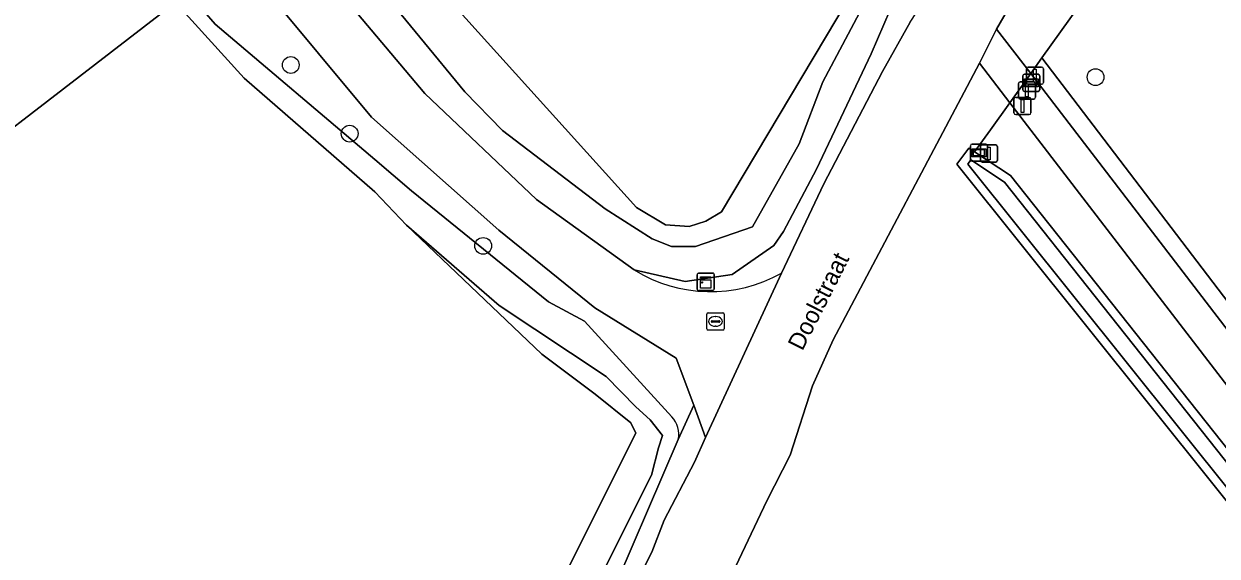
# Model space of a CAD drawing. Extents: x 164494 to 166241, y 382475 to 384495.
# Drawn here: x 164979.6 to 165049.1, y 382956.1 to 382987.1 of the extents above; entities that cross this region are included whole.
import ezdxf

# ---------------------------------------------------------------- set-up
doc = ezdxf.new("R2010")
doc.units = 0
for name, color, linetype in [('IMGEO_Afsluitpaal', 7, 'Continuous'), ('IMGEO_Boom', 7, 'Continuous'), ('IMGEO_Erf', 7, 'Continuous'), ('IMGEO_Grasland_agrarisch', 7, 'Continuous'), ('IMGEO_Grasland_overig', 7, 'Continuous'), ('IMGEO_Groenvoorziening', 7, 'Continuous'), ('IMGEO_Hek', 7, 'Continuous'), ('IMGEO_Informatiebord', 7, 'Continuous'), ('IMGEO_Kast', 7, 'Continuous'), ('IMGEO_Oever', 7, 'Continuous'), ('IMGEO_Openbare_ruimte_label', 7, 'Continuous'), ('IMGEO_Rijbaan_lokaal_gesloten', 7, 'Continuous'), ('IMGEO_Rioolput', 7, 'Continuous'), ('IMGEO_Straatnaambord', 7, 'Continuous'), ('IMGEO_Voetpad_halfverhard', 7, 'Continuous'), ('IMGEO_Waterloop', 7, 'Continuous')]:
    doc.layers.add(name, color=color, linetype=linetype)

msp = doc.modelspace()

# ---------------------------------------------------------------- linework, layer by layer
at = {"layer": 'IMGEO_Afsluitpaal'}
for p, q in [((165037.945, 382983.664), (165037.945, 382984.464)), ((165037.945, 382984.464), (165037.945, 382983.664)), ((165038.045, 382984.564), (165038.835, 382984.564)), ((165038.835, 382984.564), (165038.045, 382984.564)), ((165038.935, 382984.464), (165038.935, 382983.664)), ((165038.935, 382983.664), (165038.935, 382984.464)), ((165037.48, 382982.803), (165037.48, 382983.603)), ((165037.48, 382983.603), (165037.48, 382982.803)), ((165037.58, 382983.703), (165038.37, 382983.703)), ((165038.37, 382983.703), (165037.58, 382983.703)), ((165038.835, 382983.564), (165038.045, 382983.564)), ((165038.045, 382983.564), (165038.835, 382983.564)), ((165038.47, 382983.603), (165038.47, 382982.803)), ((165038.47, 382982.803), (165038.47, 382983.603)), ((165037.224, 382981.896), (165037.224, 382982.696)), ((165037.224, 382982.696), (165037.224, 382981.896)), ((165037.324, 382982.796), (165038.114, 382982.796)), ((165038.114, 382982.796), (165037.324, 382982.796)), ((165038.37, 382982.703), (165037.58, 382982.703)), ((165037.58, 382982.703), (165038.37, 382982.703)), ((165038.214, 382982.696), (165038.214, 382981.896)), ((165038.214, 382981.896), (165038.214, 382982.696)), ((165038.114, 382981.796), (165037.324, 382981.796)), ((165037.324, 382981.796), (165038.114, 382981.796)), ((165035.37, 382980.028), (165036.16, 382980.028)), ((165036.16, 382980.028), (165035.37, 382980.028)), ((165035.27, 382979.128), (165035.27, 382979.928)), ((165035.27, 382979.928), (165035.27, 382979.128)), ((165036.26, 382979.928), (165036.26, 382979.128)), ((165036.26, 382979.128), (165036.26, 382979.928)), ((165036.16, 382979.028), (165035.37, 382979.028)), ((165035.37, 382979.028), (165036.16, 382979.028))]:
    msp.add_line(p, q, dxfattribs=at)
for points in [[(165038.365, 382984.439), (165038.515, 382984.439), (165038.515, 382983.689), (165038.365, 382983.689), (165038.365, 382984.439)], [(165037.9, 382983.578), (165038.05, 382983.578), (165038.05, 382982.828), (165037.9, 382982.828), (165037.9, 382983.578)], [(165037.644, 382982.671), (165037.794, 382982.671), (165037.794, 382981.921), (165037.644, 382981.921), (165037.644, 382982.671)], [(165035.69, 382979.903), (165035.84, 382979.903), (165035.84, 382979.153), (165035.69, 382979.153), (165035.69, 382979.903)]]:
    msp.add_lwpolyline(points, dxfattribs=at)
for centre, start, end in [((165038.045, 382984.464), 90, 180), ((165038.045, 382984.464), 90, 180), ((165038.835, 382984.464), 0, 90), ((165038.835, 382984.464), 360, 90), ((165037.58, 382983.603), 90, 180), ((165037.58, 382983.603), 90, 180), ((165038.045, 382983.664), 180, 270), ((165038.045, 382983.664), 180, 270), ((165038.37, 382983.603), 0, 90), ((165038.37, 382983.603), 360, 90), ((165038.835, 382983.664), 270, 0), ((165038.835, 382983.664), 270, 0), ((165037.58, 382982.803), 180, 270), ((165037.58, 382982.803), 180, 270), ((165038.37, 382982.803), 270, 0), ((165038.37, 382982.803), 270, 0), ((165037.324, 382982.696), 90, 180), ((165037.324, 382982.696), 90, 180), ((165038.114, 382982.696), 0, 90), ((165038.114, 382982.696), 360, 90), ((165037.324, 382981.896), 180, 270), ((165037.324, 382981.896), 180, 270), ((165038.114, 382981.896), 270, 0), ((165038.114, 382981.896), 270, 0), ((165035.37, 382979.928), 90, 180), ((165035.37, 382979.928), 90, 180), ((165036.16, 382979.928), 0, 90), ((165036.16, 382979.928), 360, 90), ((165035.37, 382979.128), 180, 270), ((165035.37, 382979.128), 180, 270), ((165036.16, 382979.128), 270, 0), ((165036.16, 382979.128), 270, 0)]:
    msp.add_arc(centre, 0.1, start, end, dxfattribs=at)
at = {"layer": 'IMGEO_Boom'}
for centre in [(164995.114, 382984.685), (165041.974, 382983.978), (164998.544, 382980.686), (165006.318, 382974.144)]:
    msp.add_circle(centre, 0.489, dxfattribs=at)
at = {"layer": 'IMGEO_Erf'}
msp.add_lwpolyline([(164912.977, 383001.114), (164922.099, 383006.896), (164939.727, 382985.979), (164946.353, 382978.116), (164951.254, 382972.3), (164964.372, 382979.334), (164969.997, 382974.151), (164988.4, 382988.331), (164984.931, 382992.892), (164983.682, 382994.898), (164980.12, 383000), (164974.32, 383008.309), (164974.721, 383008.566), (164975.201, 383008.524), (164975.758, 383008.141), (164974.637, 383009.542), (164958.186, 383032.429), (164958.624, 383032.701), (164958.137, 383033.332), (164957.186, 383032.6), (164956.357, 383032.183), (164935.16, 383021.535), (164919.847, 383009.569), (164910.815, 383003.74)], close=True, dxfattribs=at)
for points in [[(165149.084, 382949.174), (165148.158, 382951.679), (165147.327, 382953.204), (165144.143, 382962.9), (165139.197, 382976.046), (165137.999, 382979.812), (165137.425, 382980.815), (165123.051, 383020.688), (165118.823, 383033.37), (165102.205, 383024.82), (165097.081, 383022.184), (165092.763, 383020.321), (165071.589, 383009.606), (165052.261, 382999.034), (165049.332, 382997.432), (165046.565, 382995.873), (165042.211, 382989.793), (165038.852, 382985.102), (165066.603, 382948.671), (165135.814, 382857.34)], [(165052.627, 382955.505), (165033.888, 382978.901), (165034.586, 382979.845), (165034.926, 382979.62), (165035.847, 382980.906), (165036.979, 382982.486), (165035.21, 382984.79), (165026.7, 382968.663), (165025.486, 382965.99), (165024.184, 382961.958), (165022.83, 382959.286), (165019.573, 382952.406)]]:
    msp.add_lwpolyline(points, dxfattribs=at)
at = {"layer": 'IMGEO_Grasland_agrarisch'}
msp.add_lwpolyline([(165015.068, 383038.527), (165009.03, 383072.591), (165000.629, 383105.28), (164935.939, 383078.318), (164941.019, 383069.044), (164942.895, 383066.027), (164962.537, 383037.482), (164965.976, 383039.437), (164978.568, 383020.55), (165001.867, 382991.222), (165015.247, 382976.375), (165016.924, 382975.368), (165018.308, 382975.284), (165019.273, 382975.578), (165020.196, 382976.123), (165027.578, 382988.518), (165024.542, 382992.255), (165022.647, 382995.737), (165020.576, 383000.76), (165019.166, 383008.34)], close=True, dxfattribs=at)
msp.add_lwpolyline([(164978.417, 382906.671), (164985.101, 382913.922), (164999.326, 382935.399), (165004.186, 382942.312), (165006.908, 382946.571), (165012.979, 382958.784), (165015.209, 382963.242), (165014.915, 382963.833), (165012.834, 382965.5), (165009.734, 382967.834), (165001.853, 382975.356), (165000, 382977.286), (164992.399, 382983.912), (164988.4, 382988.331), (164969.997, 382974.151)], dxfattribs=at)
at = {"layer": 'IMGEO_Grasland_overig'}
for points in [[(164978.086, 383017.145), (164979.731, 383014.456), (164985.246, 383006.707), (164990.786, 383000), (165000, 382989.514), (165005.249, 382983.12), (165007.435, 382980.868), (165013.428, 382976.295), (165016.158, 382974.56), (165017.274, 382974.114), (165018.674, 382974.106), (165021.998, 382975.247), (165024.724, 382980.091), (165026.086, 382983.698), (165028.222, 382987.725), (165027.578, 382988.518), (165020.196, 382976.123), (165019.273, 382975.578), (165018.308, 382975.284), (165016.924, 382975.368), (165015.247, 382976.375), (165001.867, 382991.222), (164978.568, 383020.55)], [(164979.355, 382905.468), (164980.096, 382906.311), (164980.625, 382906.982), (164988.585, 382917.085), (165002.824, 382937.566), (165009.708, 382948.007), (165016.119, 382960.789), (165016.533, 382962.376), (165016.761, 382963.095), (165016.048, 382964.005), (165015.202, 382964.763), (165013.474, 382966.537), (165007.243, 382970.671), (165001.853, 382975.356), (165009.734, 382967.834), (165012.834, 382965.5), (165014.915, 382963.833), (165015.209, 382963.242), (165012.979, 382958.784), (165006.908, 382946.571), (165004.186, 382942.312), (164999.326, 382935.399), (164985.101, 382913.922), (164978.417, 382906.671)]]:
    msp.add_lwpolyline(points, dxfattribs=at)
for points in [[(165036.209, 382986.774), (165036.165, 382986.697), (165035.21, 382984.79), (165036.979, 382982.486), (165038.196, 382984.186)], [(165134.51, 382858.521), (165038.196, 382984.186), (165036.979, 382982.486), (165132.894, 382857.571), (165133.054, 382857.617), (165134.517, 382857.699)]]:
    msp.add_lwpolyline(points, close=True, dxfattribs=at)
at = {"layer": 'IMGEO_Groenvoorziening'}
for points in [[(164993.635, 382989.092), (164981.184, 383005.457), (164974.637, 383009.542), (164975.758, 383008.141), (164981.443, 383000), (164989.425, 382988.568), (164990.716, 382987.061), (165000, 382979.175), (165002.138, 382977.359), (165010.119, 382970.888), (165012.212, 382969.763), (165017.299, 382964.177)], [(165029.565, 382984.303), (165031.181, 382987.173), (165031.885, 382988.24), (165030.215, 382989.551), (165029.549, 382990.073), (165028.73, 382988.684), (165029.536, 382988.299), (165030.019, 382987.907), (165028.915, 382985.327), (165025.735, 382978.625), (165023.796, 382974.977), (165023.232, 382974.16), (165020.824, 382972.474), (165018.088, 382972.069), (165015.116, 382972.749)], [(165017.672, 382962.855), (165018.575, 382964.865), (165017.56, 382967.611), (165012.813, 382970.534), (165007.238, 382975.053), (164999.815, 382981.64), (164993.635, 382989.092)], [(165023.682, 382972.564), (165026.15, 382977.763), (165029.565, 382984.303)], [(165012.194, 382948.488), (165016.136, 382956.304), (165016.846, 382958.16), (165018.624, 382961.546), (165019.27, 382962.984), (165018.575, 382964.865), (165017.672, 382962.855), (165013.257, 382952.601)]]:
    msp.add_lwpolyline(points, dxfattribs=at)
for points in [[(165042.211, 382989.793), (165039.621, 382992.313), (165038.284, 382990.391), (165036.209, 382986.774), (165038.196, 382984.186), (165038.852, 382985.102)], [(165038.196, 382984.186), (165134.51, 382858.521), (165134.517, 382857.699), (165135.308, 382857.48), (165135.814, 382857.34), (165066.603, 382948.671), (165038.852, 382985.102)], [(165131.232, 382857.093), (165132.894, 382857.571), (165036.979, 382982.486), (165035.847, 382980.906), (165034.926, 382979.62), (165037.013, 382978.237), (165054.29, 382956.447), (165062.249, 382947.031)]]:
    msp.add_lwpolyline(points, close=True, dxfattribs=at)
for centre, radius, start, end in [((165019.555, 382979.879), 8.399, 238.09319, 299.43236), ((165016.313, 382963.185), 1.398, 346.33974, 45.1729)]:
    msp.add_arc(centre, radius, start, end, dxfattribs=at)
at = {"layer": 'IMGEO_Hek'}
for points in [[(165038.852, 382985.102), (165066.603, 382948.671), (165135.814, 382857.34), (165135.308, 382857.48)], [(165035.847, 382980.906), (165034.926, 382979.62)]]:
    msp.add_lwpolyline(points, dxfattribs=at)
at = {"layer": 'IMGEO_Informatiebord'}
for p, q in [((165034.789, 382980.075), (165035.579, 382980.075)), ((165035.579, 382980.075), (165034.789, 382980.075)), ((165034.689, 382979.175), (165034.689, 382979.975)), ((165034.689, 382979.975), (165034.689, 382979.175)), ((165035.679, 382979.975), (165035.679, 382979.175)), ((165035.679, 382979.175), (165035.679, 382979.975)), ((165035.579, 382979.075), (165034.789, 382979.075)), ((165034.789, 382979.075), (165035.579, 382979.075))]:
    msp.add_line(p, q, dxfattribs=at)
for points in [[(165034.79, 382979.807), (165035.578, 382979.807), (165035.578, 382979.343), (165034.79, 382979.343), (165034.79, 382979.807)], [(165034.855, 382979.742), (165034.855, 382979.408), (165035.513, 382979.408), (165035.513, 382979.742), (165034.855, 382979.742)]]:
    msp.add_lwpolyline(points, dxfattribs=at)
for centre, start, end in [((165034.789, 382979.975), 90, 180), ((165034.789, 382979.975), 90, 180), ((165035.579, 382979.975), 0, 90), ((165035.579, 382979.975), 360, 90), ((165034.789, 382979.175), 180, 270), ((165034.789, 382979.175), 180, 270), ((165035.579, 382979.175), 270, 0), ((165035.579, 382979.175), 270, 0)]:
    msp.add_arc(centre, 0.1, start, end, dxfattribs=at)
at = {"layer": 'IMGEO_Kast'}
for p, q in [((165018.774, 382971.626), (165018.774, 382972.467)), ((165018.774, 382972.467), (165018.774, 382971.626)), ((165018.849, 382972.551), (165019.69, 382972.551)), ((165019.69, 382972.551), (165018.849, 382972.551)), ((165019.774, 382972.476), (165019.774, 382971.635)), ((165019.774, 382971.635), (165019.774, 382972.476)), ((165019.699, 382971.551), (165018.858, 382971.551)), ((165018.858, 382971.551), (165019.699, 382971.551))]:
    msp.add_line(p, q, dxfattribs=at)
for points in [[(165018.969, 382972.341), (165019.569, 382972.341), (165019.569, 382972.256), (165018.969, 382972.256), (165018.969, 382972.341)], [(165018.969, 382972.166), (165019.569, 382972.166), (165019.569, 382971.677), (165018.969, 382971.677), (165018.969, 382972.166)]]:
    msp.add_lwpolyline(points, dxfattribs=at)
msp.add_circle((165019.053, 382972.015), 0.0377, dxfattribs=at)
for centre, start, end in [((165018.852, 382972.473), 92.4484, 184.28452), ((165018.852, 382972.473), 92.4484, 184.28452), ((165019.696, 382972.473), 2.4484, 94.28452), ((165019.696, 382972.473), 2.4484, 94.28452), ((165018.852, 382971.629), 182.4484, 274.28452), ((165018.852, 382971.629), 182.4484, 274.28452), ((165019.696, 382971.629), 272.4484, 4.28452), ((165019.696, 382971.629), 272.4484, 4.28452)]:
    msp.add_arc(centre, 0.0779, start, end, dxfattribs=at)
at = {"layer": 'IMGEO_Oever'}
for points in [[(165101.952, 382894.428), (165055.083, 382954.346), (165054.29, 382956.447), (165037.013, 382978.237), (165034.926, 382979.62), (165034.586, 382979.845), (165033.888, 382978.901), (165052.627, 382955.505), (165053.916, 382953.022), (165087.093, 382910.831), (165121.757, 382865.311)], [(165122.323, 382865.411), (165087.497, 382911.144), (165054.348, 382953.3), (165053.058, 382955.785), (165034.533, 382978.913), (165034.709, 382979.151), (165036.663, 382977.856), (165053.84, 382956.192), (165054.632, 382954.092), (165101.546, 382894.117)]]:
    msp.add_lwpolyline(points, dxfattribs=at)
at = {"layer": 'IMGEO_Rijbaan_lokaal_gesloten'}
for points in [[(165022.83, 382959.286), (165024.184, 382961.958), (165025.486, 382965.99), (165026.7, 382968.663), (165035.21, 382984.79), (165036.165, 382986.697), (165036.209, 382986.774), (165038.284, 382990.391), (165039.621, 382992.313), (165039.627, 382992.322)], [(165031.181, 382987.173), (165029.565, 382984.303), (165026.15, 382977.763), (165023.682, 382972.564), (165019.27, 382962.984), (165018.624, 382961.546), (165016.846, 382958.16), (165016.136, 382956.304), (165012.194, 382948.488)], [(165019.573, 382952.406), (165022.83, 382959.286)]]:
    msp.add_lwpolyline(points, dxfattribs=at)
at = {"layer": 'IMGEO_Rioolput'}
for p, q in [((165019.345, 382969.318), (165019.345, 382970.17)), ((165019.42, 382970.244), (165020.272, 382970.244)), ((165019.604, 382969.738), (165019.604, 382969.75)), ((165020.042, 382969.701), (165019.644, 382969.701)), ((165019.647, 382969.787), (165020.045, 382969.787)), ((165019.833, 382970.024), (165019.858, 382970.024)), ((165020.088, 382969.75), (165020.088, 382969.738)), ((165020.346, 382970.17), (165020.346, 382969.318)), ((165020.272, 382969.244), (165019.42, 382969.244)), ((165019.856, 382969.464), (165019.831, 382969.464))]:
    msp.add_line(p, q, dxfattribs=at)
for points in [[(165019.345, 382969.318), (165019.345, 382970.17)], [(165019.42, 382970.244), (165020.272, 382970.244)], [(165020.346, 382970.17), (165020.346, 382969.318)], [(165020.272, 382969.244), (165019.42, 382969.244)]]:
    msp.add_lwpolyline(points, dxfattribs=at)
for centre, radius, start, end in [((165019.422, 382970.168), 0.0765, 91.55205, 178.44795), ((165019.422, 382970.168), 0.0765, 91.55205, 178.44795), ((165019.644, 382969.747), 0.0403, 85.87752, 175.75265), ((165019.641, 382969.737), 0.0366, 178.93798, 274.71019), ((165020.045, 382969.744), 0.043, 264.86636, 352.45326), ((165020.049, 382969.749), 0.0386, 1.73085, 96.63898), ((165020.27, 382970.168), 0.0765, 1.55205, 88.44795), ((165020.27, 382970.168), 0.0765, 1.55205, 88.44795), ((165019.422, 382969.32), 0.0765, 181.55205, 268.44795), ((165019.422, 382969.32), 0.0765, 181.55205, 268.44795), ((165020.27, 382969.32), 0.0765, 271.55205, 358.44795), ((165020.27, 382969.32), 0.0765, 271.55205, 358.44795)]:
    msp.add_arc(centre, radius, start, end, dxfattribs=at)
for centre, major_axis, ratio, start_param, end_param in [((165019.832, 382969.744), (-0.387, 0.002), 0.722429, 4.712389, 7.853982), ((165019.857, 382969.744), (-0.39, 0.002), 0.717154, 1.570796, 4.712389)]:
    msp.add_ellipse(centre, major_axis=major_axis, ratio=ratio, start_param=start_param, end_param=end_param, dxfattribs=at)
at = {"layer": 'IMGEO_Straatnaambord'}
for p, q in [((165037.735, 382983.245), (165037.735, 382984.045)), ((165037.735, 382984.045), (165037.735, 382983.245)), ((165037.835, 382984.145), (165038.625, 382984.145)), ((165038.625, 382984.145), (165037.835, 382984.145)), ((165038.725, 382984.045), (165038.725, 382983.245)), ((165038.725, 382983.245), (165038.725, 382984.045)), ((165038.625, 382983.145), (165037.835, 382983.145)), ((165037.835, 382983.145), (165038.625, 382983.145))]:
    msp.add_line(p, q, dxfattribs=at)
for points in [[(165037.836, 382983.877), (165038.624, 382983.877), (165038.624, 382983.413), (165037.836, 382983.413), (165037.836, 382983.877)], [(165037.901, 382983.812), (165037.901, 382983.478), (165038.559, 382983.478), (165038.559, 382983.812), (165037.901, 382983.812)]]:
    msp.add_lwpolyline(points, dxfattribs=at)
for centre, start, end in [((165037.835, 382984.045), 90, 180), ((165037.835, 382984.045), 90, 180), ((165038.625, 382984.045), 0, 90), ((165038.625, 382984.045), 360, 90), ((165037.835, 382983.245), 180, 270), ((165037.835, 382983.245), 180, 270), ((165038.625, 382983.245), 270, 0), ((165038.625, 382983.245), 270, 0)]:
    msp.add_arc(centre, 0.1, start, end, dxfattribs=at)
at = {"layer": 'IMGEO_Voetpad_halfverhard'}
for points in [[(165015.116, 382972.749), (165009.429, 382976.853), (165002.924, 382983.02), (164995.304, 382992.08), (164983.764, 383006.976), (164976.307, 383014.726), (164975.747, 383015.453), (164961.213, 383034.306), (164960.562, 383033.902), (164959.969, 383034.672), (164953.443, 383043.142), (164940.984, 383059.314), (164923.612, 383083.222), (164922.498, 383084.86), (164918.185, 383091.202)], [(164916.364, 383089.959), (164920.303, 383083.963), (164921.752, 383081.757), (164939.485, 383057.976), (164951.578, 383041.853), (164958.137, 383033.332), (164958.624, 383032.701), (164958.186, 383032.429), (164974.637, 383009.542), (164981.184, 383005.457), (164993.635, 382989.092), (164999.815, 382981.64), (165007.238, 382975.053), (165012.813, 382970.534), (165017.56, 382967.611), (165018.575, 382964.865), (165019.27, 382962.984), (165023.682, 382972.564)]]:
    msp.add_lwpolyline(points, dxfattribs=at)
msp.add_arc((165019.555, 382979.879), 8.399, 238.09319, 299.43236, dxfattribs=at)
at = {"layer": 'IMGEO_Waterloop'}
for points in [[(165017.299, 382964.177), (165012.212, 382969.763), (165010.119, 382970.888), (165002.138, 382977.359), (165000, 382979.175), (164990.716, 382987.061), (164989.425, 382988.568), (164981.443, 383000), (164975.758, 383008.141)], [(164995.304, 382992.08), (165002.924, 382983.02), (165009.429, 382976.853), (165015.116, 382972.749), (165018.088, 382972.069), (165020.824, 382972.474), (165023.232, 382974.16), (165023.796, 382974.977), (165025.735, 382978.625), (165028.915, 382985.327), (165030.019, 382987.907)], [(165028.222, 382987.725), (165026.086, 382983.698), (165024.724, 382980.091), (165021.998, 382975.247), (165018.674, 382974.106), (165017.274, 382974.114), (165016.158, 382974.56), (165013.428, 382976.295), (165007.435, 382980.868), (165005.249, 382983.12), (165000, 382989.514)], [(164988.4, 382988.331), (164992.399, 382983.912), (165000, 382977.286), (165001.853, 382975.356), (165007.243, 382970.671), (165013.474, 382966.537), (165015.202, 382964.763), (165016.048, 382964.005), (165016.761, 382963.095), (165016.533, 382962.376), (165016.119, 382960.789), (165009.708, 382948.007)], [(165101.546, 382894.117), (165054.632, 382954.092), (165053.84, 382956.192), (165036.663, 382977.856), (165034.709, 382979.151), (165034.533, 382978.913), (165053.058, 382955.785), (165054.348, 382953.3), (165087.497, 382911.144), (165122.323, 382865.411)], [(165013.257, 382952.601), (165017.672, 382962.855)]]:
    msp.add_lwpolyline(points, dxfattribs=at)
msp.add_arc((165016.313, 382963.185), 1.398, 346.33974, 45.1729, dxfattribs=at)

# ---------------------------------------------------------------- texts
at = {"layer": 'IMGEO_Openbare_ruimte_label'}
msp.add_text('Doolstraat', height=1, rotation=63.07637, dxfattribs=at).set_placement((165024.9, 382967.981))

doc.saveas('drawing.dxf')
